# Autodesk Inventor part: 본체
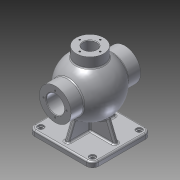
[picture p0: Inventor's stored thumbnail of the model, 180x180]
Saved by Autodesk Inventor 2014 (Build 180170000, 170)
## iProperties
Created: 2015-10
Part Number: 본체
Material: Aluminum 6061
Document SubType Name: Modeling
Designer: youjin20
Density: 2.71 g/cm^3
Appearance: Aluminum - Flat
Mass: 1509.67 g
Surface Area: 1153.69 cm^2
Volume: 557.072 cm^3
Author: youjin20
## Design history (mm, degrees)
sketch "Sketch2"
  geometry: L1 (50.5, -57.5)-(-50.5, -57.5); L2 (-62.5, -45.5)-(-62.5, 45.5); L3 (-50.5, 57.5)-(50.5, 57.5); L4 (62.5, 45.5)-(62.5, -45.5); L5 (62.5, -57.5)-(-62.5, 57.5); L6 (-62.5, -57.5)-(62.5, 57.5); A1 r 12 centre (50.5, 45.5) between (62.5, 45.5) and (50.5, 57.5); A2 r 12 centre (-50.5, 45.5) between (-50.5, 57.5) and (-62.5, 45.5); A3 r 12 centre (-50.5, -45.5) between (-62.5, -45.5) and (-50.5, -57.5); A4 r 12 centre (50.5, -45.5) between (50.5, -57.5) and (62.5, -45.5); 1 further point
  constraints: 12 end point, 8 point on circle, 8 point on line, 8 tangent, 4 centre point, 3 equal radius, 2 midpoint, 2 parallel, 1 horizontal, 1 perpendicular
  dimensions: "d0" = 125 distance of L5.end L6.end; "d1" = 115 distance of L6.start L5.end; "d2" = 12 radius of A1; "d3" = 101 distance of A2.centre A1.centre (derived)
extrude "Extrusion1" new body sketch "Sketch2" distance "d4" = 10; taper "d5" = 0 deg
sketch "Sketch3"
  geometry: A1 r 12 centre (50.5, -45.5) between (50.5, -57.5) and (62.5, -45.5) reference; A2 r 12 centre (50.5, 45.5) between (62.5, 45.5) and (50.5, 57.5) reference; A3 r 12 centre (-50.5, 45.5) between (-50.5, 57.5) and (-62.5, 45.5) reference; A4 r 12 centre (-50.5, -45.5) between (-62.5, -45.5) and (-50.5, -57.5) reference; 5 further points
  constraints: 4 coincident
hole "Hole1" sketch "Sketch3" at (-50.5, 45.5), (50.5, 45.5), (50.5, -45.5), (-50.5, -45.5) diameter "d6" = 8; stored, may be unused: countersink angle "d10" = 90 deg, drill point angle "d12" = 0 deg; dims "d7" = 6, "d8" = 12, "d9" = 3, "d11" = 8
sketch "Sketch4"
  geometry: L1 (-53, 85)-(-43, 85); L2 (-43, 85)-(43, 85); L3 (43, 85)-(53, 85); A1 r 53 centre (0, 85) between (-53, 85) and (53, 85); A2 r 43 centre (0, 85) between (-43, 85) and (43, 85); 2 further points
  constraints: 6 end point, 4 point on circle, 3 horizontal, 2 centre point, 2 coincident, 1 midpoint, 1 point on line, 1 vertical alignment
  dimensions: "d13" = 53 radius of A1; "d14" = 43 radius of A2; "d15" = 85 distance of point (0, 0) A2.centre
revolve "Revolution1" sketch "Sketch4" stored, may be unused: angle "d16" = 90 deg
workplane "Work Plane1"
sketch "Sketch5"
  geometry: C1 r 27 at (0, 0); 1 further point
  constraints: 1 centre point, 1 coincident
  dimensions: "d18" = 54 diameter of C1
extrude "Extrusion2" join sketch "Sketch5" stored distance "d19" = 10; taper "d20" = 0 deg
workplane "Work Plane2"
sketch "Sketch6"
  geometry: L1 (0, -27)-(0, 27) reference; L2 (0, 27)-(19.393, 27) reference; L3 (0, -27)-(19.393, -27) reference; 3 further points
  constraints: 1 horizontal alignment, 1 midpoint, 1 other
  dimensions: "d21" = 10 distance from line of point (10, 0) L1; "d120" = 27 distance from line of L3 point (10, 0) (derived)
emboss "Emboss1" sketch "Sketch6" dims "d0" = 125, "d1" = 115, "d2" = 12, "d3" = 101 (derived), "d23" = 0.5, "d24" = 0
sketch "Sketch7"
  geometry: L1 (4, 4)-(-4, 4); L2 (-4, 4)-(-4, -4); L3 (-4, -4)-(4, -4); L4 (4, -4)-(4, 4); L5 (4, 4)-(-4, -4); L6 (-4, 4)-(4, -4); 1 further point
  constraints: 12 end point, 2 midpoint, 2 parallel, 1 horizontal, 1 perpendicular
  dimensions: "d25" = 8 distance of L3.end L2.end; "d26" = 8 distance of L2.end L1.end
extrude "Extrusion3" join sketch "Sketch7" stored distance "d27" = 10; taper "d28" = 0 deg
sketch "Sketch8"
  geometry: L1 (-52.5, 10)-(-37.379, 47.426); L2 (52.5, 10)-(37.379, 47.426); L3 (62.5, 10)-(50.5, 10) reference; L4 (62.5, 0)-(62.5, 10) reference; L5 (-50.5, 10)-(-62.5, 10) reference; L6 (-62.5, 0)-(-62.5, 10) reference; A1 r 53 centre (0, 85) between (-27, 130.607) and (27, 130.607) reference; 1 further point
  constraints: 4 end point, 2 point on circle, 2 point on line
  dimensions: "d29" = 22 deg angle of L6 L1; "d30" = 22 deg angle of L2 L4; "d31" = 10 distance of L5.end L1.start; "d32" = 10 distance of L3.start L2.start
feature "Rib1" dims "d33" = 1, "d34" = 8, "d35" = 0, "d36" = 0, "d37" = 1, "d38" = 1
feature "Rib2" dims "d39" = 1, "d40" = 8, "d41" = 0, "d42" = 0, "d43" = 1, "d44" = 1
sketch "Sketch9"
  geometry: L1 (10, 47.5)-(44.109, 33.719); L2 (10, -47.5)-(44.109, -33.719); L3 (10, 45.5)-(10, 57.5) reference; L4 (0, 57.5)-(10, 57.5) reference; L5 (10, -57.5)-(10, -45.5) reference; L6 (0, -57.5)-(10, -57.5) reference; A1 r 53 centre (85, 0) between (130.607, 27) and (130.607, -27) reference; 1 further point
  constraints: 4 end point, 2 point on circle, 2 point on line
  dimensions: "d45" = 22 deg angle of L4 L1; "d46" = 22 deg angle of L2 L6; "d47" = 10 distance of L5.start L2.start; "d48" = 10 distance from line of L4 L1.start
feature "Rib3" dims "d49" = 1, "d50" = 8, "d51" = 0, "d52" = 0, "d53" = 1, "d54" = 1
feature "Rib4" dims "d55" = 1, "d56" = 8, "d57" = 0, "d58" = 0, "d59" = 1, "d60" = 1
workplane "Work Plane3"
sketch "Sketch10"
  geometry: L1 (-50.5, 0)-(50.5, 0) reference; C1 r 31 at (0, 85); 1 further point
  constraints: 1 centre point, 1 vertical alignment
  dimensions: "d62" = 62 diameter of C1; "d63" = 85 distance from line of L1 C1.centre
extrude "Extrusion4" join sketch "Sketch10" stored distance "d64" = 10; taper "d65" = 0 deg
fillet "Fillet1" dims "d66" = 3
sketch "Sketch11"
  geometry: C1 r 31 at (0, 0) reference; C2 r 17.5 at (0, 0); 1 further point
  constraints: 1 centre point, 1 coincident
  dimensions: "d67" = 35 diameter of C2
extrude "Extrusion5" cut sketch "Sketch11" stored distance "d68" = 10; taper "d69" = 0 deg
mirror "Mirror1"
sketch "Sketch12"
  geometry: L1 (54, -68)-(116, -68) reference; L2 (85, -38.465)-(85, -68); L3 (85, -38.465)-(102.5, -38.465); L4 (102.5, -38.465)-(102.5, -50.25); L5 (102.5, -50.25)-(103.5, -50.25); L6 (103.5, -50.25)-(103.5, -52); L7 (103.5, -52)-(102.5, -52); L8 (102.5, -52)-(102.5, -68); L9 (102.5, -68)-(85, -68); L10 (102.5, 39.278)-(67.5, 39.278) reference; 1 further point
  constraints: 16 end point, 5 perpendicular, 3 parallel, 2 midpoint, 1 collinear, 1 point on line
  dimensions: "d70" = 35 diameter of L8 L2; "d71" = 16 distance between parallel lines of L1 L7; "d72" = 37 diameter of L6 L2; "d73" = 1.75 distance from line of L7.end L5
revolve "Revolution2" sketch "Sketch12" stored, may be unused: angle "d74" = 90 deg
sketch "Sketch13" dims "d75" = 45
  geometry: C1 r 31 at (0, 0) reference; 6 further points
  constraints: 2 vertical alignment, 1 coincident, 7 other
  dimensions: "d78" = 360 deg dimension on point (0, 0) point (0, 22.5) (derived)
hole "Hole2" sketch "Sketch13" at (0, 22.5), (-22.5, 0), (0, -22.5), (22.5, 0) diameter "d80" = 3.242; stored, may be unused: countersink angle "d84" = 90 deg, drill point angle "d86" = 118 deg; dims "d81" = 12, "d82" = 12, "d83" = 3, "d85" = 15
sketch "Sketch14"
  geometry: C1 r 27 at (0, 0) reference; C2 r 13 at (0, 0)
  constraints: 1 centre point, 1 coincident
  dimensions: "d87" = 26 diameter of C2
extrude "Extrusion6" cut sketch "Sketch14" stored distance "d88" = 10; taper "d89" = 0 deg
sketch "Sketch15" dims "d90" = 40
  geometry: C1 r 27 at (0, 0) reference; 5 further points
  constraints: 2 vertical alignment, 1 coincident, 7 other
  dimensions: "d93" = 360 deg dimension on point (0, 0) point (0, 20) (derived)
hole "Hole3" sketch "Sketch15" at (0, 20), (-20, 0), (0, -20), (20, 0) diameter "d95" = 3.242; stored, may be unused: countersink angle "d99" = 90 deg, drill point angle "d101" = 118 deg; dims "d96" = 9, "d97" = 12, "d98" = 3, "d100" = 11
sketch "Sketch16" dims "d102" = 48
  geometry: C1 r 31 at (0, 0) reference; 6 further points
  constraints: 2 vertical alignment, 1 coincident, 7 other
  dimensions: "d105" = 360 deg dimension on point (0, 0) point (0, 24) (derived)
hole "Hole4" sketch "Sketch16" at (0, 24), (-24, 0), (0, -24), (24, 0) diameter "d107" = 3.242; stored, may be unused: countersink angle "d111" = 90 deg, drill point angle "d113" = 118 deg; dims "d108" = 16, "d109" = 12, "d110" = 3, "d112" = 19
fillet "Fillet2" dims "d114" = 3
fillet "Fillet3" dims "d115" = 3
fillet "Fillet4" dims "d116" = 3
chamfer "Chamfer1" distance "d117" = 1; stored, may be unused: second distance "d118" = 2, angle "d119" = 45 deg
body "Solid1"
node "Projected Loop1"
other parameters: "d61" = 68
